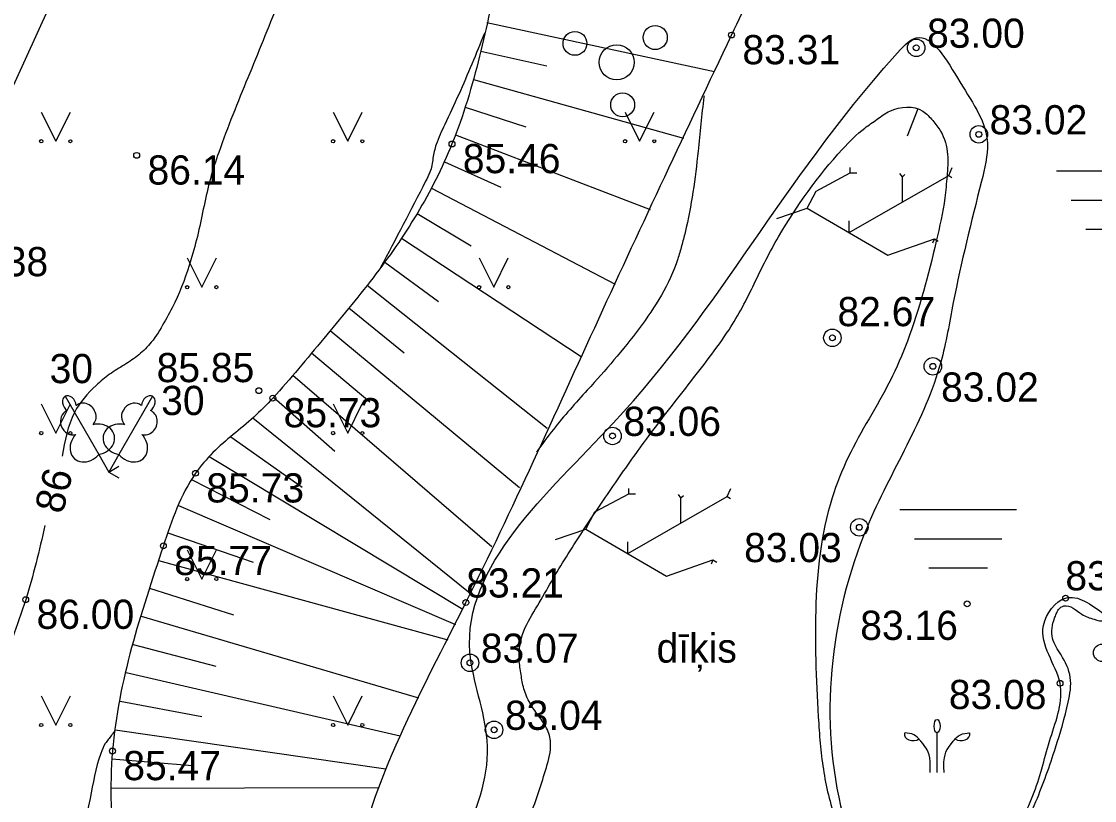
# Model space of a CAD drawing. Extents: x 576692 to 577659, y 273254 to 273799.
# Drawn here: x 576769.41 to 576787.79, y 273693.71 to 273707.05 of the extents above; entities that cross this region are included whole.
import ezdxf

# ---------------------------------------------------------------- set-up
doc = ezdxf.new("R2010")
doc.units = 0
for name, color, linetype in [('APGR_SARK_####_####_#', 7, 'Continuous'), ('BUVE_BALK_####_####_#', 7, 'Continuous'), ('BUVE_EKAS_ADRS_TKST_#', 7, 'Continuous'), ('CELI_CAPM_####_####_#', 7, 'Continuous'), ('ELEK_STUT_####_####_#', 7, 'Continuous'), ('GAZE_ELEM_####_####_#', 7, 'Continuous'), ('GAZE_VADP_ZSPD_TKST_#', 7, 'Continuous'), ('GEOD_ELEM_####_TKST_#', 7, 'Continuous'), ('GEOD_SITP_####_TKST_#', 7, 'Continuous'), ('HIDT_REZV_####_TKST_#', 7, 'Continuous'), ('LKAN_ELEM_PAST_TKST_#', 7, 'Continuous'), ('LKAN_VADP_PAST_####_I', 7, 'Continuous'), ('NORB_ZOGS_ZSTP_####_#', 7, 'Continuous'), ('RELJ_ELEM_####_####_#', 7, 'Continuous'), ('RELJ_HORZ_PAMT_####_#', 7, 'Continuous'), ('SAKT_ELEM_####_####_#', 7, 'Continuous')]:
    doc.layers.add(name, color=color, linetype=linetype)

msp = doc.modelspace()

# ---------------------------------------------------------------- linework, layer by layer
at = {"layer": 'BUVE_BALK_####_####_#'}
msp.add_spline([(576782.165, 273708.137), (576783.95, 273710.479), (576789.067, 273713.35), (576794.137, 273713.592), (576795.387, 273711.643), (576794.689, 273706.213), (576795.309, 273704.079), (576796.881, 273702.579)], degree=3, dxfattribs=at)
at = {"layer": 'BUVE_EKAS_ADRS_TKST_#'}
for p, q in [((576783.026, 273704.147), (576783.607, 273704.458)), ((576783.607, 273704.458), (576783.607, 273704.549)), ((576783.607, 273704.458), (576783.721, 273704.458)), ((576785.294, 273704.412), (576785.352, 273704.548)), ((576783.588, 273703.435), (576785.294, 273704.412)), ((576784.5, 273704.392), (576784.455, 273704.447)), ((576784.5, 273704.392), (576784.543, 273704.428)), ((576784.5, 273703.957), (576784.5, 273704.392)), ((576785.294, 273704.412), (576785.349, 273704.379)), ((576782.87, 273703.854), (576783.026, 273704.147)), ((576782.352, 273703.675), (576782.87, 273703.854)), ((576782.87, 273703.854), (576784.25, 273703.048)), ((576783.588, 273703.435), (576783.588, 273703.635)), ((576784.25, 273703.048), (576785.048, 273703.326)), ((576785.048, 273703.326), (576785.017, 273703.253)), ((576785.048, 273703.326), (576785.116, 273703.286)), ((576779.234, 273698.649), (576779.815, 273698.96)), ((576779.815, 273698.96), (576779.815, 273699.051)), ((576779.815, 273698.96), (576779.929, 273698.96)), ((576780.708, 273698.894), (576780.663, 273698.949)), ((576781.502, 273698.914), (576781.56, 273699.05)), ((576779.796, 273697.937), (576781.502, 273698.914)), ((576780.708, 273698.894), (576780.751, 273698.93)), ((576780.708, 273698.459), (576780.708, 273698.894)), ((576781.502, 273698.914), (576781.557, 273698.881)), ((576779.078, 273698.356), (576779.234, 273698.649)), ((576778.56, 273698.177), (576779.078, 273698.356)), ((576779.078, 273698.356), (576780.458, 273697.55)), ((576779.796, 273697.937), (576779.796, 273698.137)), ((576780.458, 273697.55), (576781.256, 273697.828)), ((576781.256, 273697.828), (576781.225, 273697.755)), ((576781.256, 273697.828), (576781.324, 273697.788))]:
    msp.add_line(p, q, dxfattribs=at)
for centre in [(576784.738, 273706.601), (576785.809, 273705.118), (576783.302, 273701.633), (576785.023, 273701.144), (576779.535, 273699.952), (576783.762, 273698.386), (576787.924, 273696.237), (576777.094, 273696.066), (576777.507, 273694.917)]:
    msp.add_circle(centre, 0.15, dxfattribs=at)
at = {"layer": 'CELI_CAPM_####_####_#'}
msp.add_lwpolyline([(576773.869, 273658.741), (576773.854, 273658.784), (576773.503, 273659.803), (576770.984, 273666.605), (576766.299, 273679.057), (576764.543, 273683.538), (576764.259, 273684.554), (576764.25, 273685.513), (576764.288, 273686.523), (576764.428, 273692.633), (576764.527, 273693.163), (576767.396, 273701.827), (576768.01, 273703.188), (576772.621, 273713.302), (576777.579, 273724.305)], dxfattribs=at)
at = {"layer": 'ELEK_STUT_####_####_#'}
msp.add_line((576784.588, 273705.093), (576784.771, 273705.559), dxfattribs=at)
msp.add_spline([(576781.655, 273660.674), (576781.598, 273660.841), (576781.246, 273662.068), (576780.848, 273663.8), (576780.402, 273666.21), (576780.006, 273668.093), (576779.82, 273668.587), (576779.56, 273669.054), (576779.287, 273669.515), (576779.059, 273669.996), (576778.44, 273671.764), (576778.09, 273672.972), (576777.724, 273674.128), (576777.507, 273674.603), (576777.226, 273675.05), (576776.94, 273675.497), (576776.71, 273675.971), (576776.267, 273677.75), (576776.076, 273679.036), (576776.026, 273679.68), (576776.013, 273680.317), (576776.135, 273681.001), (576776.4, 273681.673), (576776.676, 273682.346), (576776.833, 273683.032), (576776.94, 273683.888), (576776.846, 273685.038), (576776.734, 273685.836), (576776.505, 273687.076), (576776.58, 273687.714), (576777.345, 273691.31), (576777.594, 273692.158), (576777.931, 273692.99), (576778.258, 273693.812), (576778.387, 273694.222), (576778.476, 273694.632), (576778.436, 273694.883), (576778.29, 273695.128), (576778.123, 273695.373), (576778.016, 273695.622), (576777.97, 273695.864), (576777.937, 273696.12), (576778.016, 273696.611), (576778.25, 273697.042), (576778.494, 273697.466), (576779.008, 273698.293), (576779.552, 273699.101), (576780.118, 273699.898), (576780.834, 273700.829), (576781.192, 273701.294), (576781.531, 273701.771), (576781.761, 273702.157), (576781.963, 273702.559), (576782.162, 273702.965), (576782.379, 273703.361), (576783.474, 273704.863), (576783.856, 273705.225), (576784.068, 273705.377), (576784.286, 273705.517), (576784.851, 273705.517), (576785.021, 273705.353), (576785.155, 273705.173), (576785.275, 273704.774), (576785.265, 273704.403), (576785.227, 273704.029), (576785.081, 273703.29), (576784.586, 273701.576), (576784.291, 273700.897), (576783.929, 273700.245), (576783.574, 273699.588), (576783.297, 273698.89), (576783.016, 273696.963), (576783.02, 273695.989), (576783.067, 273695.021), (576783.103, 273694.576), (576783.165, 273694.134), (576783.262, 273693.693), (576783.403, 273693.254), (576783.559, 273692.883), (576783.7, 273692.679), (576783.864, 273692.517), (576784.389, 273692.292), (576784.815, 273692.256), (576785.363, 273692.3), (576785.72, 273692.399), (576786.083, 273692.578), (576786.32, 273692.795), (576786.541, 273693.149), (576786.789, 273693.689), (576787.124, 273694.61), (576787.341, 273695.392), (576787.377, 273695.816), (576787.218, 273696.205), (576787.074, 273696.483), (576787.107, 273696.831), (576787.137, 273696.903), (576787.172, 273696.976), (576787.268, 273697.039), (576787.575, 273696.898), (576787.783, 273696.811), (576787.97, 273696.784), (576788.258, 273697.005), (576788.726, 273697.259), (576788.891, 273697.319), (576789.063, 273697.36), (576789.236, 273697.403), (576789.401, 273697.467), (576789.749, 273697.734), (576790.384, 273698.531), (576790.511, 273699.039), (576790.337, 273699.768), (576790.207, 273700.029), (576790.044, 273700.273), (576789.916, 273700.542), (576789.829, 273700.785), (576789.807, 273701.355), (576789.883, 273702.115), (576790.097, 273704.111), (576790.331, 273705.756), (576790.518, 273706.867), (576790.939, 273708.386), (576791.702, 273710.052), (576792.372, 273711.212), (576792.879, 273711.925), (576793.213, 273712.22), (576793.487, 273712.3), (576793.574, 273712.039), (576792.942, 273711.019), (576792.547, 273710.348), (576791.875, 273708.874), (576791.381, 273707.59), (576791.167, 273706.727), (576790.932, 273705.121), (576790.685, 273703.227), (576790.531, 273701.648), (576790.551, 273700.812), (576790.839, 273700.176), (576791.1, 273699.581), (576791.187, 273698.919), (576790.953, 273698.183), (576790.404, 273697.42), (576789.99, 273697.018), (576789.2, 273696.657), (576789, 273696.592), (576788.794, 273696.544), (576788.391, 273696.383), (576788.224, 273696.035), (576788.159, 273695.335), (576788.071, 273694.134), (576788.04, 273693.651), (576788.048, 273693.294), (576788.244, 273692.639), (576788.558, 273692.026), (576788.879, 273691.706), (576791.459, 273689.649), (576797.983, 273684.662), (576799.135, 273683.867), (576801.011, 273683.002), (576803.058, 273681.765), (576804.293, 273680.709), (576804.792, 273680.043), (576805.327, 273678.757), (576805.553, 273678.31), (576805.969, 273678.02), (576806.825, 273678.223), (576807.172, 273678.313), (576807.866, 273678.514), (576808.167, 273678.535), (576808.272, 273678.469), (576808.197, 273678.35), (576807.951, 273678.238), (576807.574, 273678.036), (576806.891, 273677.751), (576805.749, 273677), (576805.859, 273676.057), (576805.969, 273675.349), (576806.013, 273675.146), (576806.17, 273674.787), (576806.278, 273674.737), (576806.635, 273674.761), (576807.015, 273674.811), (576807.159, 273674.831), (576807.999, 273674.897), (576808.295, 273674.667), (576808.082, 273674.136), (576807.366, 273673.959), (576807.092, 273673.91), (576806.672, 273673.746), (576806.654, 273673.413), (576806.748, 273673.021), (576807.171, 273671.649), (576807.647, 273670.487), (576808.044, 273670.213), (576808.672, 273670.123), (576809.15, 273670.231), (576809.443, 273670.518), (576809.814, 273671.033), (576810.125, 273671.338), (576810.52, 273671.326), (576811.279, 273670.985), (576811.309, 273670.751), (576811.088, 273670.769), (576810.585, 273670.883), (576810.179, 273670.793), (576809.683, 273670.351), (576809.055, 273669.639), (576809.049, 273669.178), (576809.294, 273668.939), (576811.028, 273668.029)], degree=3, dxfattribs=at)
at = {"layer": 'GAZE_ELEM_####_####_#'}
for p, q in [((576777.385, 273707.033), (576781.285, 273706.195)), ((576777.279, 273706.544), (576778.412, 273706.293)), ((576777.156, 273706.06), (576780.752, 273705.05)), ((576777.012, 273705.581), (576778.052, 273705.247)), ((576776.847, 273705.109), (576780.18, 273703.83)), ((576776.656, 273704.647), (576777.623, 273704.211)), ((576776.437, 273704.198), (576779.58, 273702.554)), ((576776.19, 273703.763), (576777.115, 273703.206)), ((576775.922, 273703.341), (576778.996, 273701.314)), ((576775.638, 273702.93), (576776.555, 273702.254)), ((576775.332, 273702.534), (576778.418, 273700.085)), ((576775.019, 273702.144), (576775.967, 273701.374)), ((576774.702, 273701.757), (576777.941, 273699.068)), ((576774.382, 273701.374), (576775.381, 273700.536)), ((576774.058, 273700.993), (576777.47, 273698.058)), ((576773.73, 273700.615), (576774.779, 273699.693)), ((576773.377, 273700.261), (576777.099, 273697.258)), ((576772.996, 273699.938), (576774.222, 273699.074)), ((576772.626, 273699.602), (576776.971, 273696.986)), ((576772.326, 273699.203), (576773.663, 273698.518)), ((576772.099, 273698.758), (576776.845, 273696.723)), ((576771.918, 273698.292), (576773.38, 273697.788)), ((576771.76, 273697.818), (576776.714, 273696.457)), ((576771.607, 273697.342), (576773.045, 273696.889)), ((576771.461, 273696.864), (576776.214, 273695.465)), ((576771.326, 273696.382), (576772.743, 273696.007)), ((576771.205, 273695.897), (576775.9, 273694.816)), ((576771.101, 273695.408), (576772.501, 273695.144)), ((576771.017, 273694.915), (576775.65, 273694.247)), ((576770.957, 273694.419), (576772.34, 273694.305)), ((576770.939, 273693.919), (576775.526, 273693.931))]:
    msp.add_line(p, q, dxfattribs=at)
msp.add_spline([(576791.053, 273723.247), (576786.777, 273723.358), (576785.853, 273723.331), (576784.941, 273723.192), (576784.038, 273722.93), (576783.59, 273722.749), (576783.142, 273722.532), (576782.382, 273722.029), (576781.761, 273721.406), (576781.269, 273720.685), (576781.069, 273720.293), (576780.897, 273719.883), (576780.716, 273719.093), (576780.667, 273718.284), (576780.617, 273717.482), (576780.432, 273716.715), (576780.102, 273715.97), (576779.933, 273715.597), (576779.779, 273715.22), (576779.019, 273713.137), (576778.296, 273711.041), (576777.889, 273709.532), (576777.585, 273707.993), (576777.259, 273706.456), (576777.049, 273705.699), (576776.786, 273704.953), (576776.187, 273703.759), (576775.433, 273702.661), (576774.588, 273701.62), (576773.716, 273700.6), (576773.39, 273700.273), (576773.037, 273699.974), (576772.692, 273699.666), (576772.393, 273699.312), (576771.842, 273698.068), (576770.97, 273694.555), (576770.948, 273693.639), (576771.025, 273692.723), (576771.358, 273690.891), (576771.727, 273689.057), (576771.881, 273687.681), (576771.889, 273687.222), (576771.79, 273685.908), (576771.593, 273684.593), (576771.405, 273683.278), (576771.329, 273681.964), (576771.349, 273681.138), (576771.414, 273680.312), (576771.818, 273678.693), (576772.486, 273677.158), (576773.173, 273675.669), (576774.529, 273672.707), (576776.378, 273668.434), (576777.175, 273665.767), (576777.124, 273663.311), (576777.146, 273662.692), (576777.166, 273662.192), (576777.203, 273661.694), (576777.268, 273661.219), (576777.358, 273660.706), (576777.37, 273660.64), (576777.435, 273660.343), (576777.477, 273660.152), (576777.586, 273659.664), (576777.697, 273659.176)], degree=3, dxfattribs=at)
at = {"layer": 'GEOD_ELEM_####_TKST_#'}
for points in [[(576777.701, 273714.932), (576776.834, 273713.466), (576775.822, 273711.558), (576774.957, 273709.861), (576774.364, 273708.621), (576773.812, 273707.362), (576773.29, 273706.089), (576772.79, 273704.809), (576772.647, 273704.357), (576772.539, 273703.894), (576772.438, 273703.428), (576772.315, 273702.967), (576772.037, 273702.237), (576771.853, 273701.89), (576771.636, 273701.556), (576771.423, 273701.343), (576771.176, 273701.171), (576770.922, 273701.008), (576770.69, 273700.818), (576770.321, 273700.355), (576770.11, 273699.607)], [(576769.814, 273698.416), (576769.484, 273697.147), (576769.036, 273695.829), (576768.776, 273694.957), (576768.536, 273694.457), (576768.227, 273693.996), (576767.515, 273693.131), (576767.316, 273692.908), (576767.109, 273692.694), (576766.903, 273692.479), (576766.705, 273692.255), (576766.177, 273691.487), (576765.772, 273690.482), (576765.619, 273689.681), (576765.503, 273688.879), (576765.419, 273688.075), (576765.366, 273687.267), (576765.305, 273684.386), (576765.538, 273681.038)]]:
    msp.add_spline(points, degree=3, dxfattribs=at)
at = {"layer": 'GEOD_SITP_####_TKST_#'}
for points in [[(576777.342, 273706.849), (576777.126, 273706.322), (576776.662, 273705.286), (576776.515, 273704.943), (576776.46, 273704.708), (576776.441, 273704.587), (576776.408, 273704.471), (576776.335, 273704.314), (576775.563, 273702.835)], [(576781.104, 273705.778), (576781.102, 273705.763), (576781.001, 273704.83), (576780.779, 273703.439), (576780.72, 273703.211), (576780.653, 273702.983), (576779.993, 273701.793), (576779.104, 273700.737), (576778.523, 273700.065), (576778.234, 273699.676)], [(576771.012, 273694.903), (576770.897, 273694.749), (576770.848, 273694.681), (576770.769, 273694.511), (576770.586, 273693.743), (576769.497, 273689.762), (576769.267, 273688.405), (576769.27, 273687.222), (576769.378, 273686.039), (576769.501, 273684.856), (576769.548, 273683.673), (576769.52, 273683.23), (576769.451, 273682.81), (576769.357, 273682.394), (576769.262, 273681.979), (576769.188, 273681.562), (576769.176, 273680.6), (576769.604, 273678.839), (576769.869, 273677.731), (576769.979, 273677.003), (576770.021, 273676.635), (576770.081, 273676.271), (576770.793, 273673.833), (576771.261, 273672.65), (576771.782, 273671.484), (576771.987, 273671.135), (576772.039, 273670.993), (576772.601, 273667.751), (576772.598, 273666.644), (576772.546, 273666.09), (576772.472, 273665.54), (576772.28, 273664.711), (576771.998, 273663.9)]]:
    msp.add_spline(points, degree=3, dxfattribs=at)
at = {"layer": 'LKAN_ELEM_PAST_TKST_#'}
for p, q in [((576769.75, 273705.5), (576770, 273705)), ((576770, 273705), (576770.25, 273705.5)), ((576774.75, 273705.5), (576775, 273705)), ((576775, 273705), (576775.25, 273705.5)), ((576779.75, 273705.5), (576780, 273705)), ((576780, 273705), (576780.25, 273705.5)), ((576787.143, 273704.493), (576789.143, 273704.493)), ((576787.393, 273703.993), (576788.893, 273703.993)), ((576787.643, 273703.493), (576788.643, 273703.493)), ((576772.25, 273703), (576772.5, 273702.5)), ((576772.5, 273702.5), (576772.75, 273703)), ((576777.25, 273703), (576777.5, 273702.5)), ((576777.5, 273702.5), (576777.75, 273703)), ((576769.75, 273700.5), (576770, 273700)), ((576770, 273700), (576770.25, 273700.5)), ((576774.75, 273700.5), (576775, 273700)), ((576775, 273700), (576775.25, 273700.5)), ((576770.735, 273699.633), (576770.908, 273699.332)), ((576771.081, 273699.633), (576770.908, 273699.332)), ((576770.908, 273699.332), (576771.081, 273699.432)), ((576770.908, 273699.332), (576771.081, 273699.232)), ((576784.456, 273698.692), (576786.456, 273698.692)), ((576784.706, 273698.192), (576786.206, 273698.192)), ((576772.25, 273698), (576772.5, 273697.5)), ((576772.5, 273697.5), (576772.75, 273698)), ((576784.956, 273697.692), (576785.956, 273697.692)), ((576769.75, 273695.5), (576770, 273695)), ((576770, 273695), (576770.25, 273695.5)), ((576774.75, 273695.5), (576775, 273695)), ((576775, 273695), (576775.25, 273695.5)), ((576785.095, 273694.186), (576785.095, 273694.867))]:
    msp.add_line(p, q, dxfattribs=at)
for points in [[(576770.158, 273700.631), (576770.735, 273699.633)], [(576771.658, 273700.631), (576771.081, 273699.633)], [(576770.352, 273700.475), (576770.35, 273700.475)], [(576771.619, 273700.385), (576771.619, 273700.386)]]:
    msp.add_lwpolyline(points, dxfattribs=at)
for centre, radius in [((576778.892, 273706.676), 0.204), ((576780.267, 273706.777), 0.207), ((576779.606, 273706.352), 0.301), ((576779.709, 273705.624), 0.205), ((576769.75, 273705), 0.028), ((576770.25, 273705), 0.0263), ((576774.75, 273705), 0.028), ((576775.25, 273705), 0.0263), ((576779.75, 273705), 0.028), ((576780.25, 273705), 0.0263), ((576772.25, 273702.5), 0.028), ((576772.75, 273702.5), 0.0263), ((576777.25, 273702.5), 0.028), ((576777.75, 273702.5), 0.0263), ((576769.75, 273700), 0.028), ((576770.25, 273700), 0.0263), ((576774.75, 273700), 0.028), ((576775.25, 273700), 0.0263), ((576772.25, 273697.5), 0.028), ((576772.75, 273697.5), 0.0263), ((576769.75, 273695), 0.028), ((576770.25, 273695), 0.0263), ((576774.75, 273695), 0.028), ((576775.25, 273695), 0.0263)]:
    msp.add_circle(centre, radius, dxfattribs=at)
for centre, major_axis, ratio, start_param, end_param in [((576770.233, 273700.501), (0.075, -0.13), 0.707107, 3.14537, 5.287485), ((576770.233, 273700.501), (0.075, -0.13), 0.707107, 0.995701, 3.137816), ((576771.583, 273700.501), (-0.075, -0.13), 0.707107, 3.14537, 5.287485), ((576771.583, 273700.501), (-0.075, -0.13), 0.707107, 0.995701, 3.137816), ((576770.492, 273700.31), (0.14, -0.165), 0.861323, 0, 3.141593), ((576771.324, 273700.31), (-0.14, -0.165), 0.861323, 3.141593, 6.283185), ((576770.269, 273700.182), (0.073, -0.203), 0.861323, 3.141593, 6.283185), ((576771.547, 273700.182), (-0.073, -0.203), 0.861323, 0, 3.141593), ((576770.689, 273699.89), (-0.313, -0.071), 0.814445, 1.531171, 4.712389), ((576771.127, 273699.89), (0.313, -0.071), 0.814445, 1.570796, 4.752015), ((576770.534, 273699.801), (0.218, 0.236), 0.814445, 1.570796, 4.752015), ((576771.282, 273699.801), (-0.218, 0.236), 0.814445, 1.531171, 4.712389), ((576784.681, 273694.844), (-0.147, 0), 0.769466, 6.117242, 8.627806), ((576785.509, 273694.844), (0.147, 0), 0.769466, 3.938565, 6.449128)]:
    msp.add_ellipse(centre, major_axis=major_axis, ratio=ratio, start_param=start_param, end_param=end_param, dxfattribs=at)
msp.add_ellipse((576785.095, 273694.981), major_axis=(0, 0.114), ratio=0.447069, dxfattribs=at)
for points in [[(576784.784, 273694.763), (576784.746, 273694.803), (576784.679, 273694.858), (576784.54, 273694.866), (576784.536, 273694.862)], [(576784.974, 273694.186), (576784.997, 273694.474), (576784.881, 273694.651), (576784.791, 273694.754), (576784.784, 273694.763)], [(576785.216, 273694.186), (576785.193, 273694.474), (576785.309, 273694.651), (576785.399, 273694.754), (576785.407, 273694.763)], [(576785.407, 273694.763), (576785.444, 273694.803), (576785.512, 273694.858), (576785.65, 273694.866), (576785.654, 273694.862)]]:
    msp.add_open_spline(points, degree=3, dxfattribs=at)
at = {"layer": 'LKAN_VADP_PAST_####_I'}
msp.add_spline([(576781.501, 273660.635), (576781.496, 273660.65), (576781.455, 273660.779), (576781.275, 273661.357), (576780.828, 273663.211), (576780.123, 273666.836), (576779.986, 273667.411), (576779.861, 273667.85), (576779.768, 273668.105), (576779.181, 273669.215), (576778.472, 273670.451), (576777.851, 273673.122), (576777.538, 273674.065), (576775.93, 273676.904), (576775.509, 273677.797), (576775.401, 273679.642), (576775.37, 273680.519), (576775.604, 273681.014), (576776.206, 273681.628), (576776.467, 273682.088), (576776.752, 273682.97), (576776.844, 273683.941), (576776.692, 273685.467), (576776.546, 273686.299), (576776.429, 273686.931), (576776.367, 273687.274), (576775.96, 273687.442), (576775.277, 273687.548), (576774.978, 273687.628), (576775.079, 273688.182), (576775.262, 273688.735), (576776.124, 273691.449), (576777.389, 273694.737), (576777.094, 273696.247), (576779.545, 273700.17), (576784.37, 273706.465), (576784.738, 273706.771), (576785.485, 273706.019), (576785.956, 273704.96), (576785.856, 273704.317), (576785.373, 273702.238), (576785.159, 273701.215), (576783.895, 273698.386), (576783.48, 273693.464), (576783.621, 273693.041), (576783.797, 273692.76), (576784.337, 273692.438), (576785.992, 273692.705), (576786.226, 273692.911), (576786.555, 273693.398), (576786.759, 273693.851), (576787.04, 273694.781), (576787.201, 273695.715), (576786.917, 273696.707), (576787.297, 273697.174), (576787.96, 273696.896)], degree=3, dxfattribs=at)
at = {"layer": 'RELJ_ELEM_####_####_#'}
for centre in [(576781.575, 273706.819), (576784.738, 273706.601), (576785.809, 273705.118), (576776.786, 273704.953), (576771.385, 273704.758), (576783.302, 273701.633), (576785.023, 273701.144), (576773.477, 273700.727), (576773.716, 273700.6), (576779.535, 273699.952), (576772.393, 273699.312), (576783.762, 273698.386), (576771.842, 273698.068), (576769.484, 273697.147), (576777.024, 273697.098), (576785.61, 273697.075), (576787.297, 273697.174), (576777.094, 273696.066), (576787.201, 273695.715), (576777.507, 273694.917), (576770.97, 273694.555)]:
    msp.add_circle(centre, 0.05, dxfattribs=at)
at = {"layer": 'SAKT_ELEM_####_####_#'}
msp.add_spline([(576781.202, 273661.318), (576780.974, 273662.21), (576780.316, 273665.645), (576779.839, 273667.799), (576779.595, 273668.354), (576779.079, 273669.26), (576778.162, 273671.093), (576777.891, 273672.78), (576777.488, 273674.065), (576776.96, 273675.037), (576775.871, 273676.897), (576775.37, 273677.874), (576775.257, 273678.364), (576775.133, 273679.739), (576775.03, 273681.114), (576774.961, 273682.49), (576774.938, 273683.867), (576774.87, 273687.097), (576774.815, 273687.689), (576774.984, 273690.271), (576775.018, 273691.339), (576775.059, 273691.873), (576775.087, 273692.139), (576775.122, 273692.406), (576775.896, 273694.808), (576777.024, 273697.098), (576779.3, 273701.959), (576781.575, 273706.819), (576782.904, 273709.89), (576783.054, 273710.383), (576783.121, 273710.894), (576783.116, 273711.95), (576783.095, 273713.018), (576783.268, 273714.057), (576783.685, 273714.889), (576783.983, 273715.248), (576784.343, 273715.563), (576785.305, 273716.116), (576786.325, 273716.506), (576787.343, 273716.859), (576787.832, 273717.061), (576788.297, 273717.301), (576788.701, 273717.648), (576789.074, 273718.078), (576789.469, 273718.444), (576789.938, 273718.601), (576790.426, 273718.77)], degree=3, dxfattribs=at)

# ---------------------------------------------------------------- texts
at = {"layer": 'APGR_SARK_####_####_#'}
for p in [(576769.708, 273700.856), (576771.619, 273700.31)]:
    msp.add_text(' 30', height=0.5, dxfattribs=at).set_placement(p)
at = {"layer": 'GAZE_VADP_ZSPD_TKST_#'}
msp.add_text('dīķis', height=0.5, dxfattribs=at).set_placement((576780.291, 273696.069))
at = {"layer": 'HIDT_REZV_####_TKST_#'}
for s, p in [(' 83.31', (576781.575, 273706.319)), (' 85.46', (576776.786, 273704.453)), (' 86.14', (576771.385, 273704.258)), (' 86.38', (576768.01, 273702.688)), (' 85.85', (576771.541, 273700.873)), (' 85.73', (576773.716, 273700.1)), (' 85.73', (576772.393, 273698.812)), (' 85.77', (576771.842, 273697.568)), (' 83.21', (576776.845, 273697.184)), (' 83.08', (576787.107, 273697.307)), (' 86.00', (576769.484, 273696.647)), (' 83.16', (576783.593, 273696.458)), (' 83.08', (576785.111, 273695.273)), (' 85.47', (576770.97, 273694.055))]:
    msp.add_text(s, height=0.5, dxfattribs=at).set_placement(p)
at = {"layer": 'NORB_ZOGS_ZSTP_####_#'}
for s, p in [(' 83.00', (576784.738, 273706.601)), (' 83.02', (576785.809, 273705.118)), (' 82.67', (576783.203, 273701.832)), (' 83.02', (576784.978, 273700.539)), (' 83.06', (576779.535, 273699.952)), (' 83.03', (576781.604, 273697.79)), (' 83.07', (576777.094, 273696.066)), (' 83.04', (576777.507, 273694.917))]:
    msp.add_text(s, height=0.5, dxfattribs=at).set_placement(p)
at = {"layer": 'RELJ_HORZ_PAMT_####_#'}
msp.add_text('86', height=0.5, rotation=76.0338, dxfattribs=at).set_placement((576770.117, 273698.598))

doc.saveas('drawing.dxf')
